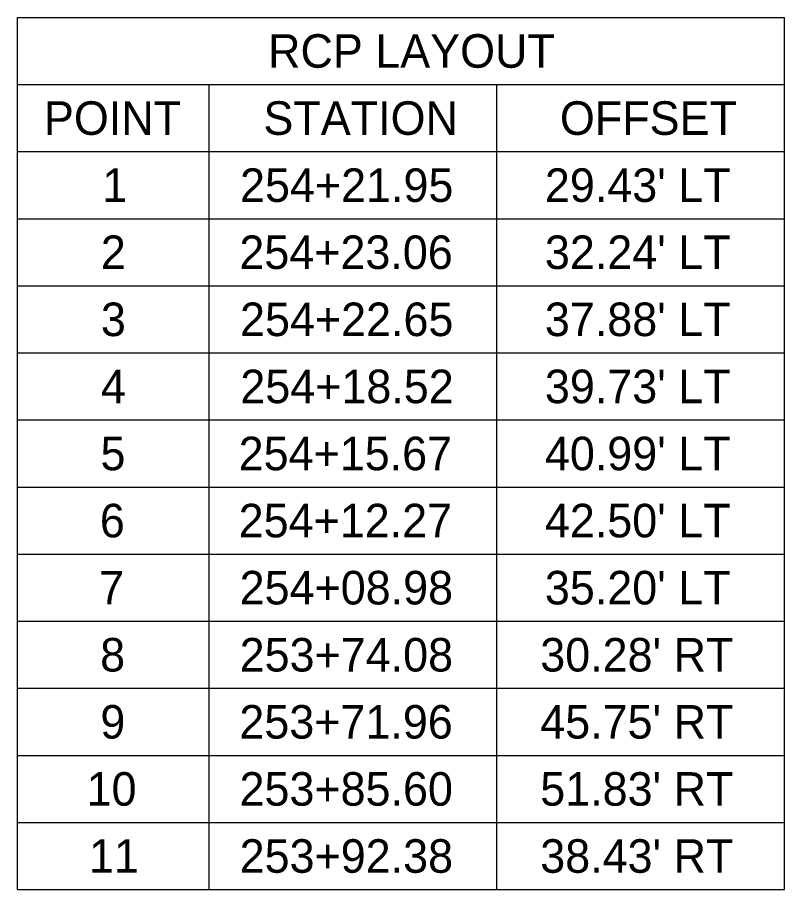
# Model space of a CAD drawing. Extents: x 0 to 2700, y -8 to 220.
# Drawn here: x 205.17 to 237.17, y 88.98 to 125.38 of the extents above; entities that cross this region are included whole.
import ezdxf

# ---------------------------------------------------------------- set-up
doc = ezdxf.new("R2010")
doc.units = 0
doc.layers.add('MT_P_Cells', color=7, linetype='Continuous')
doc.layers.add('MT_P_Work_Area', color=7, linetype='Continuous')

msp = doc.modelspace()

# ---------------------------------------------------------------- linework, layer by layer
at = {"layer": 'MT_P_Cells'}
for p, q in [((205.171, 125.385), (237.171, 125.385)), ((205.171, 88.985), (205.171, 125.385)), ((237.171, 88.985), (237.171, 125.385)), ((205.171, 122.585), (237.171, 122.585)), ((213.171, 88.985), (213.171, 122.585)), ((225.171, 88.985), (225.171, 122.585)), ((205.171, 119.785), (237.171, 119.785)), ((205.171, 116.985), (237.171, 116.985)), ((205.171, 114.185), (237.171, 114.185)), ((205.171, 111.385), (237.171, 111.385)), ((205.171, 108.585), (237.171, 108.585)), ((205.171, 105.785), (237.171, 105.785)), ((205.171, 102.985), (237.171, 102.985)), ((205.171, 100.185), (237.171, 100.185)), ((205.171, 97.385), (237.171, 97.385)), ((205.171, 94.585), (237.171, 94.585)), ((205.171, 91.785), (237.171, 91.785)), ((205.171, 88.985), (237.171, 88.985))]:
    msp.add_line(p, q, dxfattribs=at)

# ---------------------------------------------------------------- texts
for s, p in [('RCP LAYOUT', (215.627, 123.285)), ('POINT', (206.277, 120.485)), ('1', (208.713, 117.685)), ('2', (208.649, 114.885)), ('3', (208.653, 112.085)), ('4', (208.653, 109.285)), ('5', (208.636, 106.485)), ('6', (208.609, 103.685)), ('7', (208.58, 100.885)), ('8', (208.621, 98.085)), ('9', (208.629, 95.285)), ('10', (208.057, 92.485)), ('11', (208.155, 89.685))]:
    msp.add_text(s, height=1.4, dxfattribs=at).set_placement(p)
at = {"layer": 'MT_P_Work_Area'}
for s, p in [('STATION', (215.433, 120.485)), ('OFFSET', (227.8, 120.485)), ('254+21.95', (214.456, 117.685)), ("29.43' LT", (227.174, 117.685)), ('254+23.06', (214.429, 114.885)), ("32.24' LT", (227.174, 114.885)), ('254+22.65', (214.456, 112.085)), ("37.88' LT", (227.174, 112.085)), ('254+18.52', (214.469, 109.285)), ("39.73' LT", (227.174, 109.285)), ('254+15.67', (214.4, 106.485)), ("40.99' LT", (227.174, 106.485)), ('254+12.27', (214.4, 103.685)), ("42.50' LT", (227.174, 103.685)), ('254+08.98', (214.441, 100.885)), ("35.20' LT", (227.174, 100.885)), ('253+74.08', (214.441, 98.085)), ("30.28' RT", (226.98, 98.085)), ('253+71.96', (214.429, 95.285)), ("45.75' RT", (226.98, 95.285)), ('253+85.60', (214.435, 92.485)), ("51.83' RT", (226.98, 92.485)), ('253+92.38', (214.441, 89.685)), ("38.43' RT", (226.98, 89.685))]:
    msp.add_text(s, height=1.4, dxfattribs=at).set_placement(p)

doc.saveas('drawing.dxf')
